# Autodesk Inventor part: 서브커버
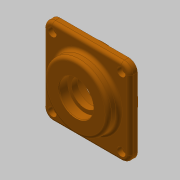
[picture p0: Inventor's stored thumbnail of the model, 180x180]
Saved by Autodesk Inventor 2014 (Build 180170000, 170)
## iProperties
Created: 2018-09
Part Number: 서브커버
Material: 알루미늄 6061
Document SubType Name: Modeling
Designer: mduedu
Density: 2.71 g/cm^3
Appearance: 주황색
Mass: 206.511 g
Surface Area: 197.007 cm^2
Volume: 76.2032 cm^3
Author: mduedu
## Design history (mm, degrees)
sketch "스케치1"
  geometry: L1 (-40, -40)-(40, -40); L2 (40, -40)-(40, 40); L3 (40, 40)-(-40, 40); L4 (-40, 40)-(-40, -40); L5 (-40, -40)-(40, 40); L6 (40, -40)-(-40, 40); 1 further point
  constraints: 12 end point, 2 midpoint, 2 parallel, 1 horizontal, 1 perpendicular
  dimensions: "d0" = 80 distance of L3.end L2.end; "d1" = 80 distance of L2.end L1.end
extrude "돌출1" new body sketch "스케치1" distance "d2" = 7; taper "d3" = 0 deg
sketch "스케치2"
  geometry: C1 r 30 at (0, 0); 1 further point
  constraints: 1 centre point, 1 coincident
  dimensions: "d4" = 60 diameter of C1
extrude "돌출2" join sketch "스케치2" distance "d5" = 10; taper "d6" = 0 deg
sketch "스케치3"
  geometry: C1 r 32.5 at (0, 0); 1 further point
  constraints: 1 centre point, 1 coincident
  dimensions: "d7" = 65 diameter of C1
extrude "돌출3" join sketch "스케치3" distance "d8" = 9; taper "d9" = 0 deg
sketch "스케치4"
  geometry: L1 (-32.5, -9)-(32.5, -9) reference; L2 (30, 17)-(-30, 17) reference; L3 (0, 17)-(0, -9); L4 (0, -9)-(20, -9); L5 (20, -9)-(20, 3); L6 (20, 3)-(0, 3); L7 (0, 3)-(0, -9); L8 (0, 3)-(12.5, 3); L9 (12.5, 3)-(12.5, 8.7); L10 (12.5, 8.7)-(0, 8.7); L11 (0, 8.7)-(0, 3); L12 (0, 8.7)-(16, 8.7); L13 (16, 8.7)-(16, 17); L14 (16, 17)-(0, 17); L15 (0, 17)-(0, 8.7); 1 further point
  constraints: 26 end point, 6 parallel, 3 horizontal, 3 perpendicular, 2 midpoint, 1 point on line
  dimensions: "d10" = 12 distance of L4.end L5.end; "d12" = 8.3 distance of L12.end L13.end; "d13" = 32 diameter of L13 L3; "d14" = 25 diameter of L9 L3; "d15" = 40 diameter of L5 L3
revolve "회전1" sketch "스케치4" stored, may be unused: angle "d16" = 90 deg
fillet "모깎기1" dims "d17" = 8
fillet "모깎기2" dims "d18" = 3
fillet "모깎기3" dims "d19" = 3
chamfer "모따기1" distance "d20" = 0.8; stored, may be unused: second distance "d21" = 2, angle "d22" = 30 deg
chamfer "모따기2" distance "d23" = 1; stored, may be unused: second distance "d24" = 2, angle "d25" = 30 deg
fillet "모깎기4" dims "d26" = 0.3
sketch "스케치5"
  geometry: A1 r 8 centre (-32, 32) between (-32, 40) and (-40, 32) reference; A2 r 8 centre (-32, -32) between (-40, -32) and (-32, -40) reference; A3 r 8 centre (32, -32) between (32, -40) and (40, -32) reference; A4 r 8 centre (32, 32) between (40, 32) and (32, 40) reference; 5 further points
  constraints: 4 coincident
hole "구멍1" sketch "스케치5" at (-32, 32), (32, 32), (32, -32), (-32, -32) diameter "d27" = 4.5; stored, may be unused: countersink angle "d31" = 90 deg, drill point angle "d33" = 118 deg; dims "d28" = 6, "d29" = 8, "d30" = 4.4, "d32" = 8
node "솔리드1"
